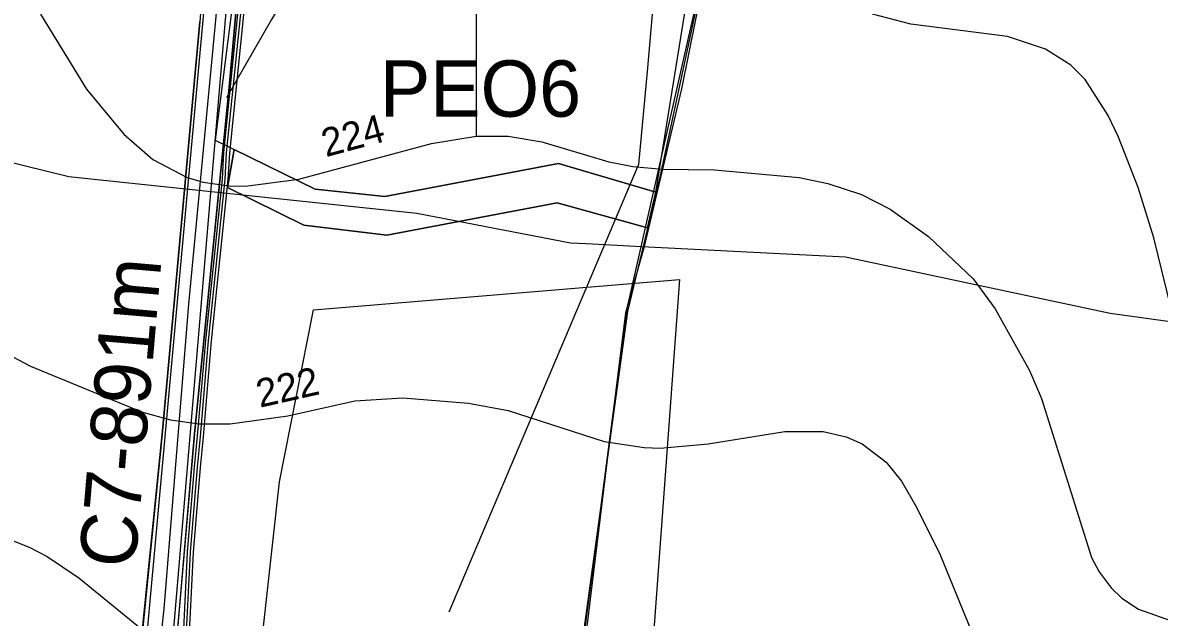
# Model space of a CAD drawing. Extents: x -662500 to -653478, y -1056827 to -1049993.
# Drawn here: x -660199.8 to -659796.6, y -1053777.2 to -1053566.3 of the extents above; entities that cross this region are included whole.
import ezdxf

# ---------------------------------------------------------------- set-up
doc = ezdxf.new("R2010")
doc.units = 0
for name, color, linetype in [('58', 7, 'Continuous'), ('Vrstva 1', 7, 'Continuous'), ('Vrstva 11', 7, 'Continuous'), ('Vrstva 17', 7, 'Continuous'), ('Vrstva 18', 7, 'Continuous'), ('Vrstva 22', 7, 'Continuous'), ('Vrstva 24', 7, 'Continuous'), ('Vrstva 35', 7, 'Continuous'), ('Vrstva 36', 7, 'Continuous'), ('Vrstva 37', 7, 'Continuous'), ('Vrstva 42', 7, 'Continuous'), ('Vrstva 47', 7, 'Continuous'), ('Vrstva 5', 7, 'Continuous'), ('Vrstva 57', 7, 'Continuous'), ('Vrstva 6', 7, 'Continuous'), ('Vrstva 61', 7, 'Continuous'), ('Vrstva 7', 7, 'Continuous')]:
    doc.layers.add(name, color=color, linetype=linetype)

msp = doc.modelspace()

# ---------------------------------------------------------------- linework, layer by layer
at = {"layer": '58'}
msp.add_lwpolyline([(-659953.41, -1053526.41), (-659966.09, -1053589.8), (-659979.45, -1053646.11), (-659986.05, -1053669.16), (-659992.56, -1053722.27), (-660000.86, -1053790.13), (-660001.11, -1053794.15), (-660003.29, -1053815.65), (-660003.85, -1053821.48), (-660005.39, -1053836.92), (-660006.52, -1053846.84), (-660007.35, -1053857.17), (-660010.12, -1053854.58), (-660021.49, -1053851.7), (-660054.09, -1053851.84), (-660060.83, -1053852), (-660057.69, -1053873.59), (-660041.94, -1053978.1), (-660074.73, -1053978.95), (-660077.64, -1053979.02), (-660077.87, -1053999.08)], dxfattribs=at)
at = {"layer": 'Vrstva 1'}
msp.add_lwpolyline([(-659954.06, -1053529.13), (-659973.69, -1053620.54), (-659985.28, -1053668.78), (-660002.01, -1053790.13)], dxfattribs=at)
at = {"layer": 'Vrstva 11'}
msp.add_lwpolyline([(-660128.59, -1053535.41), (-660141.02, -1053666.13), (-660149.73, -1053774.2), (-660154.88, -1053820.83), (-660155.97, -1053836.63), (-660155.9, -1053844.5)], dxfattribs=at)
at = {"layer": 'Vrstva 17'}
msp.add_lwpolyline([(-660093.08, -1053291.6), (-660096.38, -1053299.54), (-660103.97, -1053335.5), (-660111.56, -1053371.46), (-660148.84, -1053810.53)], dxfattribs=at)
at = {"layer": 'Vrstva 22'}
msp.add_lwpolyline([(-660124.86, -1053611.33), (-660096.1, -1053625.4), (-660071.37, -1053627.99), (-660009.78, -1053616.2), (-659975.27, -1053626.43), (-659978.23, -1053639.12), (-660010.19, -1053630.18), (-660070.69, -1053641.68), (-660100.07, -1053638.13), (-660127.22, -1053624.79)], close=True, dxfattribs=at)
at = {"layer": 'Vrstva 24'}
msp.add_lwpolyline([(-659687, -1053701.5), (-659711, -1053686.5), (-659734.5, -1053680.5), (-659814, -1053669.5), (-659908, -1053649.5), (-659980.14, -1053645.8), (-660000, -1053644.78), (-660005.5, -1053644.5), (-660060, -1053634), (-660183.5, -1053621), (-660246.5, -1053605.5), (-660263.5, -1053598), (-660330, -1053557), (-660364, -1053532.5), (-660389, -1053520), (-660401.5, -1053515), (-660430, -1053509.5)], dxfattribs=at)
at = {"layer": 'Vrstva 35'}
msp.add_lwpolyline([(-660026.37, -1053508.12), (-660038.92, -1053545.65), (-660038.92, -1053606.59)], dxfattribs=at)
at = {"layer": 'Vrstva 36'}
for points in [[(-659954.61, -1053529.84), (-659955.59, -1053526.67), (-659954.74, -1053506.97), (-659953.08, -1053482.2), (-659950.97, -1053450.72), (-659945.17, -1053422.76), (-659937.73, -1053399.42), (-659931.19, -1053378.89), (-659926.07, -1053353.49), (-660088.86, -1053281.5), (-660107.93, -1053369.91), (-660112.89, -1053460.91), (-660131.56, -1053607.96), (-660124.86, -1053611.33)], [(-659975.27, -1053626.43), (-659964.94, -1053562.8), (-659961.56, -1053542)]]:
    msp.add_lwpolyline(points, dxfattribs=at)
at = {"layer": 'Vrstva 37'}
for points in [[(-660303.5, -1053230.44), (-660268.36, -1053230.44), (-660272.06, -1053456.27), (-660238.23, -1053464.08), (-660230.1, -1053441.95), (-660156.9, -1053423.64), (-660133.56, -1053315.41), (-660112.26, -1053315.31), (-660122.32, -1053372.39), (-660125.43, -1053404.18), (-660127.57, -1053442.13), (-660131.64, -1053497.5), (-660136.95, -1053566.03), (-660150.34, -1053712.33), (-660162.69, -1053835.19), (-660383.93, -1053811.56), (-660351.89, -1053606.5)], [(-660096.66, -1053668.18), (-659966.86, -1053657.36), (-659976.74, -1053792.99), (-660022.22, -1053782.75), (-660030.23, -1053849.74), (-660120.67, -1053837.24), (-660108.76, -1053729.2)]]:
    msp.add_lwpolyline(points, close=True, dxfattribs=at)
at = {"layer": 'Vrstva 42'}
msp.add_lwpolyline([(-660142.78, -1053807.34), (-660142.8, -1053803.76), (-660140.36, -1053754.17), (-660137.85, -1053724), (-660136.78, -1053713.11), (-660133.93, -1053679.11), (-660128.02, -1053621.83), (-660127.49, -1053612.47), (-660120.96, -1053547.99), (-660119.87, -1053525.87), (-660118.25, -1053505.95), (-660116.02, -1053485.23), (-660115.83, -1053483.2)], dxfattribs=at)
at = {"layer": 'Vrstva 47'}
for points in [[(-660143.8, -1053803.74), (-660141.36, -1053754.1), (-660138.84, -1053723.91), (-660137.78, -1053713.02), (-660134.92, -1053679.02), (-660129.02, -1053621.75), (-660128.49, -1053612.4), (-660121.96, -1053547.91)], [(-660119.97, -1053548.06), (-660126.5, -1053612.55), (-660127.02, -1053621.91), (-660132.93, -1053679.2), (-660135.79, -1053713.2), (-660136.85, -1053724.09)], [(-660136.85, -1053724.09), (-660139.36, -1053754.23), (-660141.8, -1053803.78), (-660141.78, -1053807.33), (-660141.76, -1053810.72), (-660141.63, -1053815.06), (-660142.01, -1053828.02), (-660142.11, -1053835.66), (-660132.43, -1053836.41), (-660120.67, -1053837.24), (-660100.4, -1053837.97), (-660084.79, -1053838.68), (-660059.04, -1053839.7), (-660057.24, -1053839.89), (-660054.55, -1053840.13), (-660054.17, -1053840.17), (-660053.64, -1053840.74), (-660053.64, -1053841.13), (-660053.65, -1053842), (-660053.56, -1053844.32), (-660053.69, -1053848.39), (-660054.82, -1053848.28)]]:
    msp.add_lwpolyline(points, dxfattribs=at)
at = {"layer": 'Vrstva 5'}
for points in [[(-660118.91, -1053503.44), (-660126.59, -1053589.2), (-660138.85, -1053712.12), (-660146.82, -1053803.03), (-660148.64, -1053813.09), (-660149.76, -1053834.51), (-660139.06, -1053839.19), (-660076.83, -1053841.01), (-660051.64, -1053841.59), (-660032.72, -1053842.78), (-660018.51, -1053844.59), (-660012.27, -1053845.97), (-660005.29, -1053848.46), (-660004.16, -1053861.83), (-660010.2, -1053857.03), (-660012.44, -1053855.66), (-660019.03, -1053852.98), (-660026.92, -1053851.95), (-660058.85, -1053852.09), (-660122.2, -1053852.55), (-660157.09, -1053852.56), (-660239.81, -1053850.04)], [(-659953.22, -1053525.2), (-659985.7, -1053668.71), (-660001.66, -1053790.17), (-660016.06, -1053789.15), (-660016.34, -1053791.52), (-660047.13, -1053792.26), (-660051.64, -1053841.59), (-660076.83, -1053841.01), (-660072.33, -1053792.31), (-660148.64, -1053813.09), (-660146.82, -1053803.03), (-660144.24, -1053774.31), (-660138.85, -1053712.12), (-660126.59, -1053589.2), (-660118.91, -1053503.44)], [(-660659.38, -1053604.53), (-660591.82, -1053615.12), (-660481.41, -1053634.1), (-660378.28, -1053653.76), (-660398.86, -1053759.98), (-660407.77, -1053814.99), (-660406.28, -1053815.33), (-660305.92, -1053826.68), (-660234.87, -1053832.54), (-660162.97, -1053835.81), (-660159.44, -1053804.48), (-660157.5, -1053793.95), (-660158.49, -1053793), (-660150.34, -1053712.33), (-660136.95, -1053566.03)], [(-660235.12, -1053837.99), (-660159.73, -1053842.4), (-660159.25, -1053835.99), (-660162.97, -1053835.81), (-660159.44, -1053804.48), (-660157.5, -1053793.95), (-660158.49, -1053793), (-660150.34, -1053712.33), (-660136.95, -1053566.03)]]:
    msp.add_lwpolyline(points, dxfattribs=at)
at = {"layer": 'Vrstva 57'}
for points in [[(-659973.2, -1053334.93), (-659996.23, -1053399.08), (-660027.3, -1053441.49), (-660047.69, -1053475.92), (-660061.32, -1053496.6), (-660085.29, -1053521.5), (-660111.6, -1053565.21), (-660127.58, -1053592.94)], [(-659974.37, -1053345.21), (-659975.78, -1053555.05), (-659978.13, -1053582.31), (-659981.42, -1053616.61), (-660048.63, -1053775.46)]]:
    msp.add_lwpolyline(points, dxfattribs=at)
at = {"layer": 'Vrstva 6'}
msp.add_lwpolyline([(-660124.86, -1053611.33), (-660127.22, -1053624.79), (-660100.07, -1053638.13), (-660070.69, -1053641.68), (-660010.19, -1053630.18), (-659978.23, -1053639.12), (-659975.27, -1053626.43), (-660009.78, -1053616.2), (-660071.37, -1053627.99), (-660096.1, -1053625.4)], close=True, dxfattribs=at)
at = {"layer": 'Vrstva 61'}
msp.add_lwpolyline([(-660103.33, -1053285.76), (-660108.12, -1053300.67), (-660119.61, -1053361.23), (-660123.15, -1053400.36), (-660134.78, -1053552.31), (-660158.95, -1053818.23), (-660161.28, -1053838.75)], dxfattribs=at)
at = {"layer": 'Vrstva 7'}
for p, q in [((-660193.53, -1053563.23), (-660177.23, -1053589.87)), ((-659884.73, -1053566.77), (-659898.33, -1053563.23)), ((-659850.43, -1053571.16), (-659884.73, -1053566.77)), ((-659836.97, -1053575.7), (-659850.43, -1053571.16)), ((-659828.04, -1053581.37), (-659836.97, -1053575.7)), ((-659822.94, -1053586.47), (-659828.04, -1053581.37)), ((-659814.72, -1053599.22), (-659822.94, -1053586.47)), ((-660177.23, -1053589.87), (-660163.91, -1053605.88)), ((-659811.04, -1053606.88), (-659814.72, -1053599.22)), ((-660163.91, -1053605.88), (-660153.71, -1053614.81)), ((-660054.79, -1053609.14), (-660038.92, -1053606.59)), ((-660038.92, -1053606.59), (-660027.58, -1053606.59)), ((-660027.58, -1053606.59), (-660015.68, -1053608.58)), ((-659804.09, -1053624.73), (-659811.04, -1053606.88)), ((-660101.84, -1053621.76), (-660054.79, -1053609.14)), ((-660015.68, -1053608.58), (-659991.87, -1053615.66)), ((-660153.71, -1053614.81), (-660141.52, -1053621.19)), ((-659991.87, -1053615.66), (-659983.36, -1053617.36)), ((-659983.36, -1053617.36), (-659972.88, -1053618.21)), ((-659972.88, -1053618.21), (-659954.45, -1053618.5)), ((-659954.45, -1053618.5), (-659924.41, -1053621.19)), ((-660141.52, -1053621.19), (-660135.85, -1053622.89)), ((-660135.85, -1053622.89), (-660125.93, -1053624.31)), ((-660125.93, -1053624.31), (-660119.98, -1053624.17)), ((-660119.98, -1053624.17), (-660101.84, -1053621.76)), ((-659924.41, -1053621.19), (-659914.21, -1053623.31)), ((-659914.21, -1053623.31), (-659902.3, -1053627.28)), ((-659902.3, -1053627.28), (-659892.1, -1053632.39)), ((-659798.57, -1053642.59), (-659804.09, -1053624.73)), ((-659892.1, -1053632.39), (-659878.49, -1053642.16)), ((-659878.49, -1053642.16), (-659862.62, -1053657.19)), ((-659792.33, -1053668.1), (-659798.57, -1053642.59)), ((-659862.62, -1053657.19), (-659854.83, -1053667.81)), ((-659854.83, -1053667.81), (-659842.64, -1053689.64)), ((-660205.58, -1053683.69), (-660197.07, -1053688.08)), ((-660197.07, -1053688.08), (-660157.68, -1053704.38)), ((-659842.64, -1053689.64), (-659838.39, -1053699.56)), ((-660105.81, -1053705.79), (-660082, -1053700.41)), ((-660082, -1053700.41), (-660064.99, -1053699.42)), ((-660064.99, -1053699.42), (-660041.75, -1053701.26)), ((-659838.39, -1053699.56), (-659820.67, -1053755.96)), ((-660157.68, -1053704.38), (-660147.47, -1053707.21)), ((-660041.75, -1053701.26), (-660027.58, -1053703.81)), ((-660027.58, -1053703.81), (-659993.57, -1053714.86)), ((-660147.47, -1053707.21), (-660137.27, -1053708.63)), ((-660137.27, -1053708.63), (-660126.21, -1053708.63)), ((-660126.21, -1053708.63), (-660105.81, -1053705.79)), ((-659956.72, -1053715.71), (-659929.51, -1053711.32)), ((-659929.51, -1053711.32), (-659915.91, -1053711.32)), ((-659915.91, -1053711.32), (-659907.69, -1053713.16)), ((-659907.69, -1053713.16), (-659902.02, -1053715.71)), ((-659993.57, -1053714.86), (-659979.4, -1053716.99)), ((-659979.4, -1053716.99), (-659973.73, -1053717.27)), ((-659973.73, -1053717.27), (-659956.72, -1053715.71)), ((-659902.02, -1053715.71), (-659893.52, -1053722.23)), ((-659893.52, -1053722.23), (-659888.13, -1053728.89)), ((-659888.13, -1053728.89), (-659882.74, -1053738.11)), ((-659882.74, -1053738.11), (-659874.38, -1053755.11)), ((-660207.56, -1053748.31), (-660197.35, -1053752.42)), ((-660197.35, -1053752.42), (-660191.12, -1053755.68)), ((-660191.12, -1053755.68), (-660179.92, -1053763.19)), ((-659874.38, -1053755.11), (-659863.19, -1053782.32)), ((-659820.67, -1053755.96), (-659817.98, -1053761.06)), ((-659817.98, -1053761.06), (-659813.73, -1053766.73)), ((-660179.92, -1053763.19), (-660144.92, -1053791.67)), ((-659813.73, -1053766.73), (-659809.9, -1053770.42)), ((-659809.9, -1053770.42), (-659803.95, -1053774.39)), ((-659803.95, -1053774.39), (-659790.63, -1053779.06))]:
    msp.add_line(p, q, dxfattribs=at)

# ---------------------------------------------------------------- texts
at = {"layer": 'Vrstva 18'}
msp.add_text('C7-891m', height=20, rotation=85.1036, dxfattribs=at).set_placement((-660159.99, -1053760.16))
at = {"layer": 'Vrstva 22'}
msp.add_text('PEO6', height=20, rotation=360, dxfattribs=at).set_placement((-660073.1, -1053599.65))
at = {"layer": 'Vrstva 7'}
for s, rotation, p in [('224', 15.0068, (-660092.29, -1053614.02)), ('222', 12.7444, (-660115.72, -1053702.91))]:
    msp.add_text(s, height=10, rotation=rotation, dxfattribs=at).set_placement(p)

doc.saveas('drawing.dxf')
